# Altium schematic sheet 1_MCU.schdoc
size 309 x 223 mm; Symbol: Sheet-Symbol_A4; Device: Sheet-Symbol_A4; Company: EasyEDA.com; Drawed: EasyEDA Pro; Reviewed: EasyEDA Pro; Version: V0.1; Page Size: A4; @Project Name: Recovery-Board-Kaveet-Saksham-Edition; @Page Count: 3; @Update Date: 2023-08-18; @Create Date: 2023-07-25; @Schematic Name: Schematic; Part Number: JLCPCB-002; @Page No: 1; @Page Name: MCU
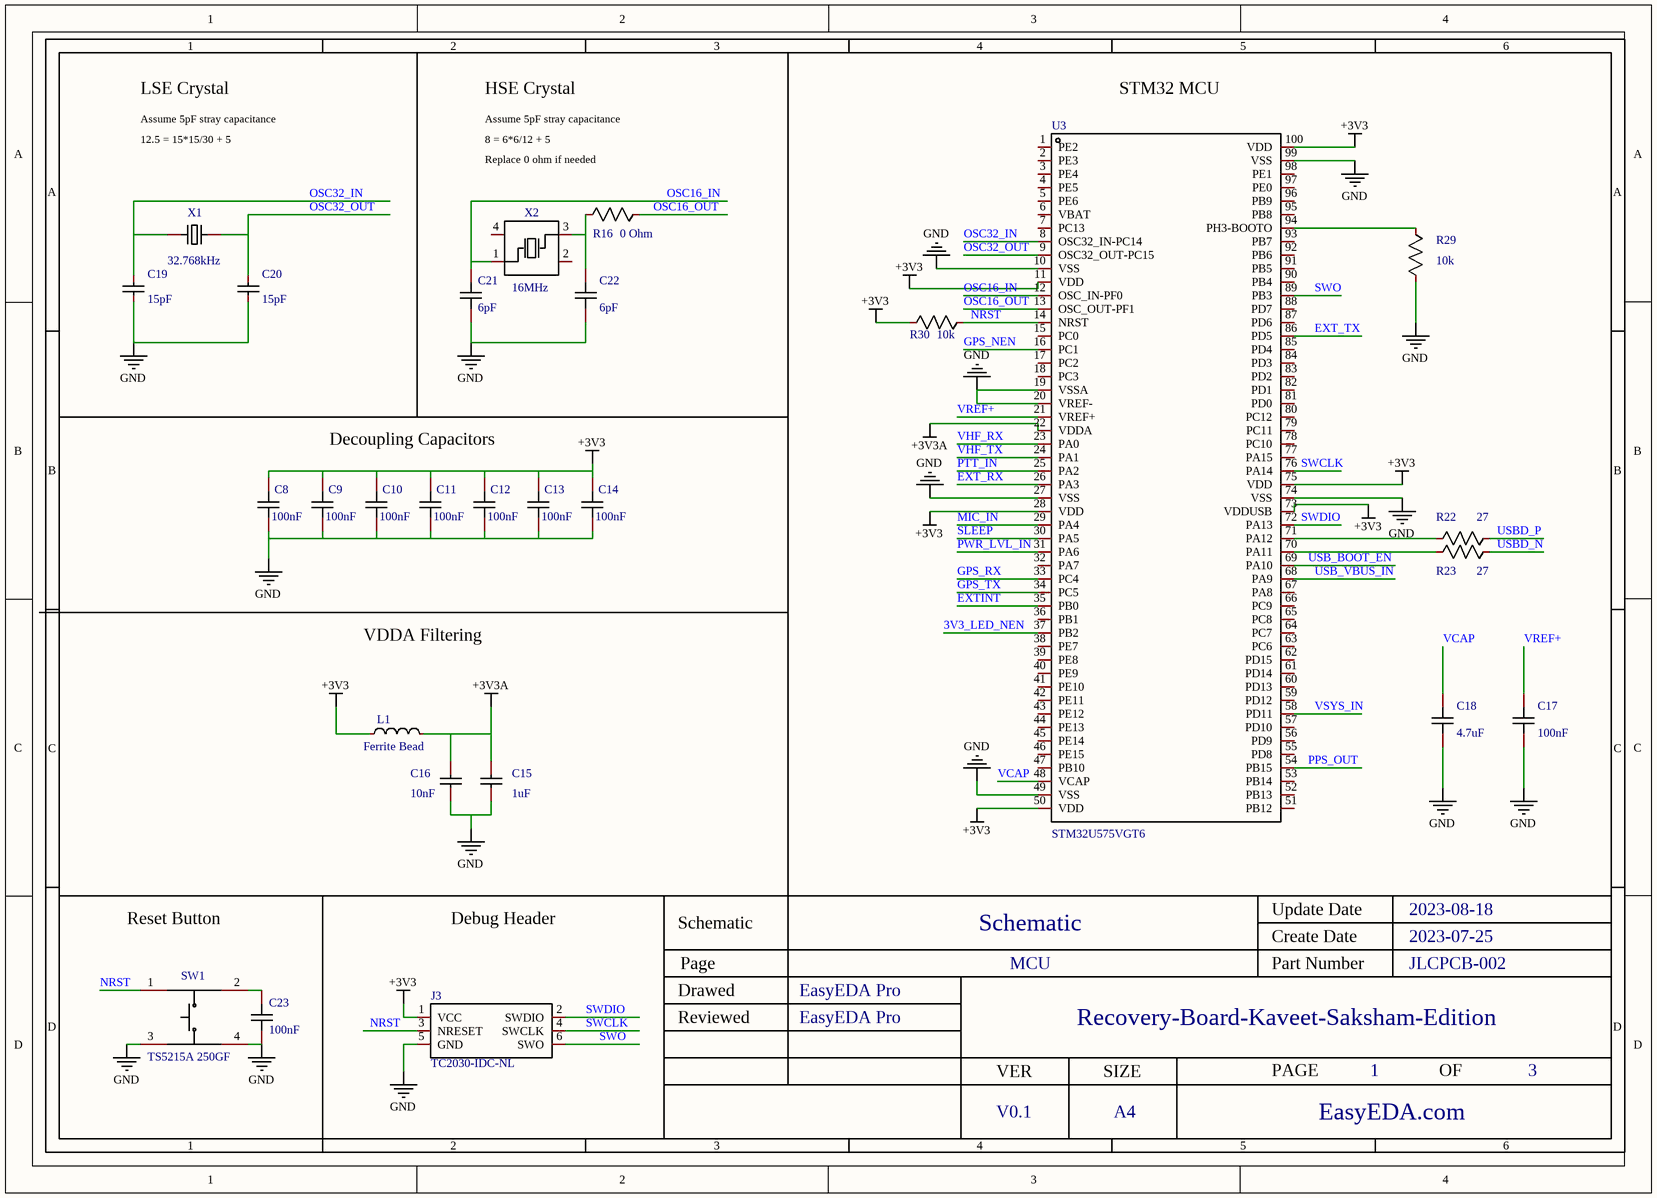
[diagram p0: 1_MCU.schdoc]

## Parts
C8  100nF  [C0402]
C9  100nF  [C0402]
C10  100nF  [C0402]
C11  100nF  [C0402]
C12  100nF  [C0402]
C13  100nF  [C0402]
C14  100nF  [C0402]
C15  1uF  [C0402]
C16  10nF  [C0402]
C17  100nF  [C0402]
C18  4.7uF  [C0603]
C19  15pF  [C0402]
C20  15pF  [C0402]
C21  6pF  [C0402]
C22  6pF  [C0402]
C23  100nF  [C0402]
J3  TC2030-IDC-NL  [TC2030-IDC-NL]
L1  Ferrite Bead  [L0603]
R16  0 Ohm
R22  27
R23  27
R29  10k
R30  10k
SW1  TS5215A 250GF  [SW-SMD_4P-L5.2-W5.2-P3.70-LS6.4]
U3  STM32U575VGT6  [LQFP-100_L14.0-W14.0-P0.50-LS16.0-BL]
X1  32.768kHz  [OSC-SMD_L3.2-W1.5]
X2  16MHz  [CRYSTAL-SMD_4P-L2.5-W2.0-BL-A]

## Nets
+3V3: C8.2 C9.2 C10.2 C11.2 C12.2 C13.2 C14.2 J3.1(VCC) L1.2 R30.1 U3.11(VDD) U3.28(VDD) U3.50(VDD) U3.73(VDDUSB) U3.75(VDD) U3.100(VDD)
+3V3A: C15.2 C16.2 L1.1 U3.22(VDDA)
GND: C8.1 C9.1 C10.1 C11.1 C12.1 C13.1 C14.1 C15.1 C16.1 C17.1 C18.1 C19.1 C20.1 C21.1 C22.1 C23.1 J3.5(GND) R29.1 SW1.3 SW1.4 U3.10(VSS) U3.19(VSSA) U3.20(VREF-) U3.27(VSS) U3.49(VSS) U3.74(VSS) U3.99(VSS)
3V3_LED_NEN: U3.37(PB2)
EXT_RX: U3.26(PA3)
EXT_TX: U3.86(PD5)
EXTINT: U3.35(PB0)
GPS_NEN: U3.16(PC1)
GPS_RX: U3.33(PC4)
GPS_TX: U3.34(PC5)
MIC_IN: U3.29(PA4)
NRST: J3.3(NRESET) R30.2 SW1.1 U3.14(NRST)
OSC16_IN: C21.2 U3.12(OSC_IN-PF0) X2.1
OSC16_OUT: R16.2 U3.13(OSC_OUT-PF1)
OSC32_IN: C19.2 U3.8(OSC32_IN-PC14) X1.1
OSC32_OUT: C20.2 U3.9(OSC32_OUT-PC15) X1.2
PPS_OUT: U3.54(PB15)
PTT_IN: U3.25(PA2)
PWR_LVL_IN: U3.31(PA6)
SLEEP: U3.30(PA5)
SWCLK: J3.4(SWCLK) U3.76(PA14)
SWDIO: J3.2(SWDIO) U3.72(PA13)
SWO: J3.6(SWO) U3.89(PB3)
USB_BOOT_EN: U3.69(PA10)
USB_VBUS_IN: U3.68(PA9)
USBD_N: R23.1
USBD_P: R22.2
VCAP: C18.2 U3.48(VCAP)
VHF_RX: U3.23(PA0)
VHF_TX: U3.24(PA1)
VREF+: C17.2 U3.21(VREF+)
VSYS_IN: U3.58(PD11)
NetC22_2: C22.2 R16.1 X2.3
NetC23_2: C23.2 SW1.2
NetR22_1: R22.1 U3.71(PA12)
NetR23_2: R23.2 U3.70(PA11)
NetR29_2: R29.2 U3.94(PH3-BOOTO)

Not connected (* = marked no-connect by the designer): U3 1(PE2) 2(PE3) 3(PE4) 4(PE5) 5(PE6) 6(VBAT) 7(PC13) 15(PC0) 17(PC2) 18(PC3) 32(PA7) 36(PB1) 38(PE7) 39(PE8) 40(PE9) 41(PE10) 42(PE11) 43(PE12) 44(PE13) 45(PE14) 46(PE15) 47(PB10) 51(PB12) 52(PB13) 53(PB14) 55(PD8) 56(PD9) 57(PD10) 59(PD12) 60(PD13) 61(PD14) 62(PD15) 63(PC6) 64(PC7) 65(PC8) 66(PC9) 67(PA8) 77(PA15) 78(PC10) 79(PC11) 80(PC12) 81(PD0) 82(PD1) 83(PD2) 84(PD3) 85(PD4) 87(PD6) 88(PD7) 90(PB4) 91(PB5) 92(PB6) 93(PB7) 95(PB8) 96(PB9) 97(PE0) 98(PE1); X2 2(GND) 4(GND)

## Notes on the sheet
- 12.5 = 15*15/30 + 5
- Assume 5pF stray capacitance
- LSE Crystal
- HSE Crystal
- 8 = 6*6/12 + 5
- (near U3) STM32 MCU
- Replace 0 ohm if needed
- Decoupling Capacitors
- VDDA Filtering
- Reset Button
- Debug Header

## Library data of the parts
C8-C14 C17 C23 = GRM155R71C104KA88D: Manufacturer: muRata(村田); Convert to PCB: yes
C15 = GRM155R61E105KA12D: Manufacturer: muRata(村田); Convert to PCB: yes
C16 = GRM155R71H103KA88D: Manufacturer: muRata(村田); Convert to PCB: yes
C18 = GRM188R61A475KE15D: Manufacturer: muRata(村田); Convert to PCB: yes
C19 C20 = GJM1555C1H150FB01D: Manufacturer: muRata(村田); Convert to PCB: yes
C21 C22 = GCM1555C1H6R0BA16D: Manufacturer: muRata(村田); Convert to PCB: yes
J3 = TC2030-IDC-NL: Add into BOM: yes; _: 3
L1 = BLM18PG121SN1D: Manufacturer: muRata(村田); Value: 120R; Convert to PCB: yes
R16 = 0603WAF0000T5E: Convert to PCB: yes; Origin Footprint: R0603
R22 R23 = RC0603FR-0710RL: Manufacturer Part: HPCR0402F27R0K9; Symbol: 10; Convert to PCB: yes; Origin Footprint: R0603
R29 = RC0603FR-0710RL: Manufacturer Part: RC0402FR-0710KL; Symbol: 10; Convert to PCB: yes; Origin Footprint: R0603
R30 = RC0603FR-0710KL: Convert to PCB: yes; Origin Footprint: R0603
SW1 = TS5215A 250gf: Contact Current:50mA Voltage Rating (DC):12V Circuit:SPST Actuator Orientation:Top触动 Actuator Style:Round Button Illumination Color:- Switch Length:5.2mm Switch Width:5.2mm; Manufacturer: SHOU HAN(首韩); Add into BOM: yes; Contact Current: 50mA; Voltage Rating (DC): 12V; Circuit: SPST; Actuator Orientation: Top触动; Switch Length: 5.2mm
U3 = STM32U575VGT6: Manufacturer: ST(意法半导体); Add into BOM: yes
X1 = X321532768KGD2SI: Manufacturer: YXC(扬兴晶振); Convert to PCB: yes
X2 = NX2520SA-16MHZ-STD-CSW-5: Manufacturer: NDK; Convert to PCB: yes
